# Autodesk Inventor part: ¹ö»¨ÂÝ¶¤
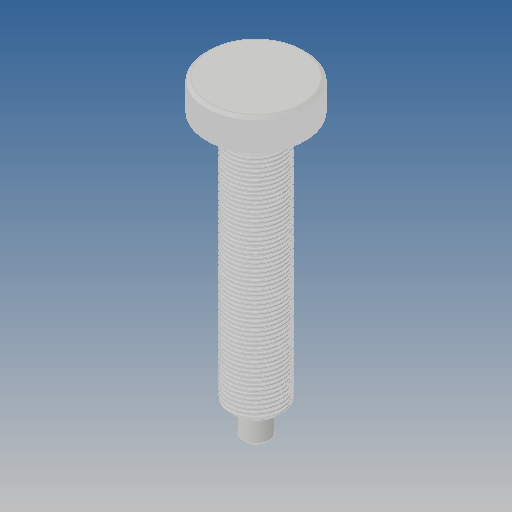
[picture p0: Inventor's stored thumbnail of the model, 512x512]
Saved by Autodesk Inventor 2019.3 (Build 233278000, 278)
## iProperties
Created: 2017-12
Part Number: ¹ö»¨ÂÝ¶¤
Material: Ogólny
Document SubType Name: Modeling
Designer: Admin
Density: 1 g/cm^3
Appearance: Domyślna
Author: Admin
Revision Number: ÈÎºÎ
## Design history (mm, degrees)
feature "ÇÐ³ý-É¨Ãè2"
node "Bryła1"
